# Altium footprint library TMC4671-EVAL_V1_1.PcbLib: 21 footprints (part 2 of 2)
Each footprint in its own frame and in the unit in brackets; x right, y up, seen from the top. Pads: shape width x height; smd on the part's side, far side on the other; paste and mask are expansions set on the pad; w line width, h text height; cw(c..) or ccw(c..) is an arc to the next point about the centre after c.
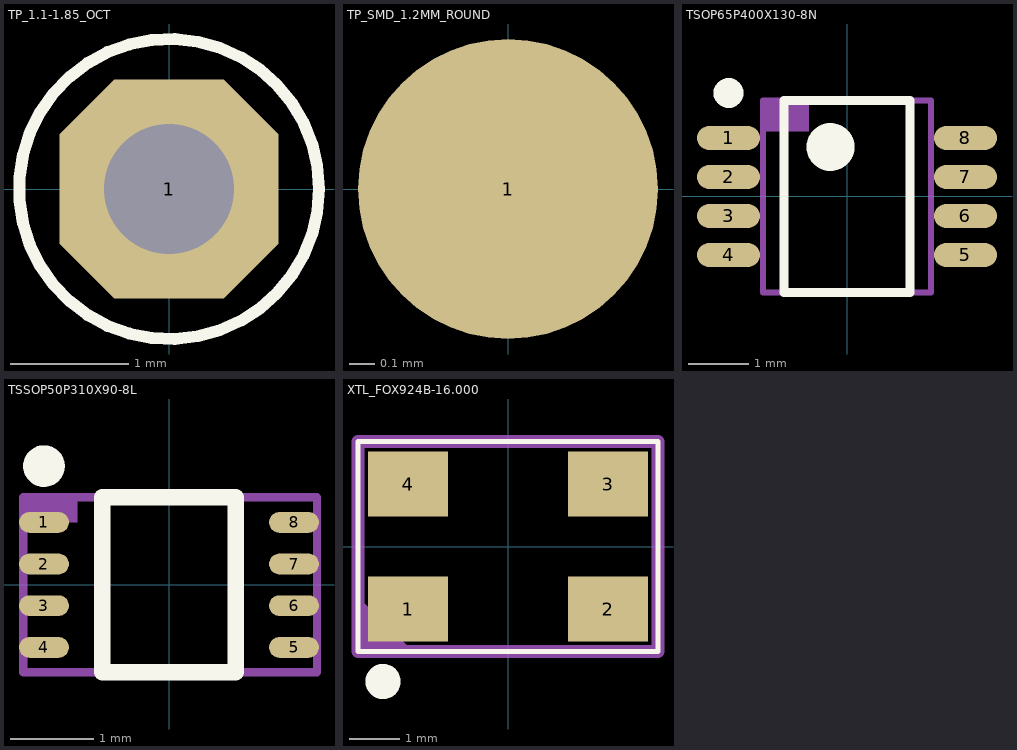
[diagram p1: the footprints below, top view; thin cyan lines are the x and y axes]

## TP_1.1-1.85_OCT [mm]
pads (1):
  oct 1.85x1.85 hole 1.1: 1(0,0)
Top Overlay:
  circle w0.1: c0,0 r1.27

## TP_SMD_1.2MM_ROUND [mm]
pads (1):
  rrect100% 1.2x1.2 smd: 1(0,0)

## TSOP65P400X130-8N [mm] "TSOP, 8-Leads, Body 2,95x2,80mm, Pitch 0,65mm, IPC Medium Density"
height 1.3
pads (8):
  oval 1.05x0.4 smd: 1(-1.975,0.975) 2(-1.975,0.325) 3(-1.975,-0.325) 4(-1.975,-0.975) 5(1.975,-0.975) 6(1.975,-0.325) 7(1.975,0.325) 8(1.975,0.975)
Top Overlay:
  circle w0.25: c-1.975,1.725 r0.125
  circle w0.4: c-0.275,0.825 r0.2
  lines w0.15: -1.05,-1.6 -1.05,1.6 1.05,1.6 1.05,-1.6 -1.05,-1.6
TopAsm:
  region: -1.397,1.6 -1.397,1.091 -0.635,1.091 -0.635,1.599
  lines w0.1: -1.397,-1.6 1.397,-1.6 1.397,1.6 -1.397,1.6 -1.397,-1.6
  text ".Designator" at 0.451,-1.236 h1
3D body "TSOP65P400X130-8N.step": height 1.3, standoff 0, extent -2,-1.6 2,1.6

## TSSOP50P310X90-8L [mm] "TSSOP, 8-Leads, Body 2,00x2,30mm, Pitch 0,50mm, IPC High Density"
height 0.9
pads (8):
  oval 0.6x0.25 smd: 1(-1.5,0.75) 2(-1.5,0.25) 3(-1.5,-0.25) 4(-1.5,-0.75) 5(1.5,-0.75) 6(1.5,-0.25) 7(1.5,0.25) 8(1.5,0.75)
Top Overlay:
  circle w0.25: c-1.5,1.425 r0.125
  lines w0.2: -0.8,-1.05 0.8,-1.05 0.8,1.05 -0.8,1.05 -0.8,-1.05
TopAsm:
  region: -1.75,1.05 -1.75,0.75 -1.1,0.75 -1.1,1.05
  lines w0.1: -1.75,-1.05 -1.75,1.05 1.775,1.05 1.775,-1.05 -1.75,-1.05
  text ".Designator" at 0.324,-0.982 h1
3D body "TSSOP50P310X90-8L.step": height 0.9, standoff 0, extent -1.549,-1.05 1.549,1.05

## XTL_FOX924B-16.000 [mm]
pads (4):
  rect 1.6x1.3 smd: 1(-2,-1.25) 2(2,-1.25) 3(2,1.25) 4(-2,1.25)
Top Overlay:
  circle w0.5: c-2.5,-2.7 r0.1
  lines w0.1: -3,-2.1 -3,0.1 -3,2.1 3,2.1 3,-2.1 -3,-2.1
TopAsm:
  region: -3,-2.1 -3,-1 -1.9,-2.1
  lines w0.254: -3,-2.1 -3,0 -3,2.1 0,2.1 3,2.1 3,0 3,-2.1 0,-2.1 -3,-2.1
3D body: height 1.5, standoff 0, extent -2.6,-1.7 2.6,1.7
